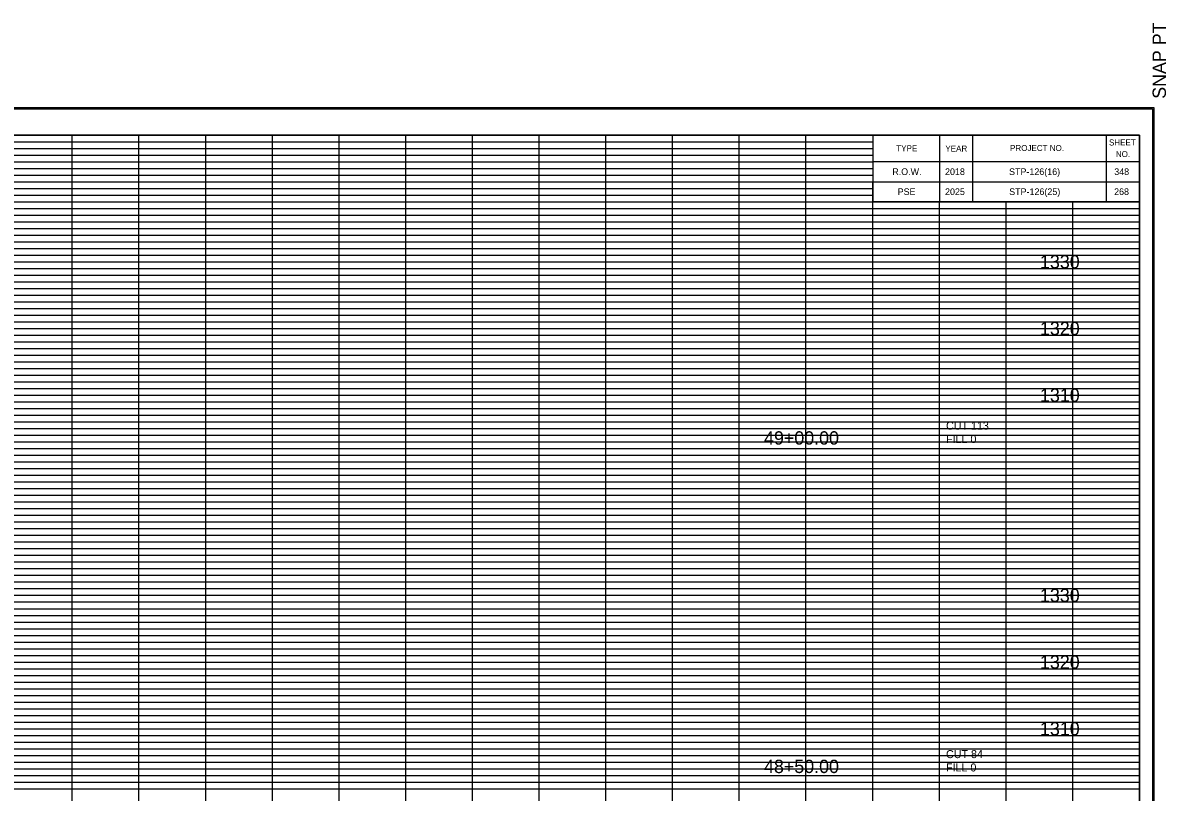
# Model space of a CAD drawing. Extents: x 980 to 1324, y 978 to 1767.
# Drawn here: x 1152.6 to 1324, y 1381.5 to 1496.8 of the extents above; entities that cross this region are included whole.
import ezdxf

# ---------------------------------------------------------------- set-up
doc = ezdxf.new("R2010")
doc.units = 0
for name, color, linetype in [('DESIGN - SCRATCH - User 1', 7, 'Continuous'), ('DESIGN - SHEET - Corner Text', 7, 'Continuous'), ('DESIGN - SHEET - Light Grid', 7, 'Continuous'), ('DESIGN - SHEET - Linework', 7, 'Continuous'), ('DESIGN - SHEET - Plot Shape', 7, 'Continuous'), ('DESIGN - TYPICAL - Text', 7, 'Continuous')]:
    doc.layers.add(name, color=color, linetype=linetype)

# ---------------------------------------------------------------- blocks, each defined once
blk = doc.blocks.new('XSTSHT')
at = {"layer": 'DESIGN - SCRATCH - User 1'}
for p, q in [((28.5, 20.45), (28.5, 20.45)), ((29.24, 20.45), (29.24, 20.45)), ((30.49, 20.45), (30.49, 20.45)), ((31.74, 20.45), (31.74, 20.45)), ((28.5, 20.15), (28.5, 20.15)), ((29.24, 20.15), (29.24, 20.15)), ((30.49, 20.15), (30.49, 20.15)), ((31.74, 20.15), (31.74, 20.15))]:
    blk.add_line(p, q, dxfattribs=at)
at = {"layer": 'DESIGN - SHEET - Light Grid'}
for p, q in [((8, 20.9), (16, 20.9)), ((8, 20.8), (16, 20.8)), ((16, 20.9), (24, 20.9)), ((16, 20.8), (24, 20.8)), ((24, 20.9), (28, 20.9)), ((24, 20.8), (28, 20.8)), ((8, 20.7), (16, 20.7)), ((8, 20.6), (16, 20.6)), ((16, 20.7), (24, 20.7)), ((16, 20.6), (24, 20.6)), ((24, 20.7), (28, 20.7)), ((24, 20.6), (28, 20.6)), ((8, 20.5), (16, 20.5)), ((8, 20.4), (16, 20.4)), ((16, 20.5), (24, 20.5)), ((16, 20.4), (24, 20.4)), ((24, 20.5), (28, 20.5)), ((24, 20.4), (28, 20.4)), ((8, 20.3), (16, 20.3)), ((16, 20.3), (24, 20.3)), ((24, 20.3), (28, 20.3)), ((8, 20.2), (16, 20.2)), ((8, 20.1), (16, 20.1)), ((16, 20.2), (24, 20.2)), ((16, 20.1), (24, 20.1)), ((24, 20.2), (28, 20.2)), ((24, 20.1), (28, 20.1)), ((8, 19.9), (16, 19.9)), ((16, 19.9), (24, 19.9)), ((24, 19.9), (32, 19.9)), ((8, 19.8), (16, 19.8)), ((16, 19.8), (24, 19.8)), ((24, 19.8), (32, 19.8)), ((8, 19.7), (16, 19.7)), ((8, 19.6), (16, 19.6)), ((16, 19.7), (24, 19.7)), ((16, 19.6), (24, 19.6)), ((24, 19.7), (32, 19.7)), ((24, 19.6), (32, 19.6)), ((8, 19.5), (16, 19.5)), ((8, 19.4), (16, 19.4)), ((16, 19.5), (24, 19.5)), ((16, 19.4), (24, 19.4)), ((24, 19.5), (32, 19.5)), ((24, 19.4), (32, 19.4)), ((8, 19.3), (16, 19.3)), ((8, 19.2), (16, 19.2)), ((16, 19.3), (24, 19.3)), ((16, 19.2), (24, 19.2)), ((24, 19.3), (32, 19.3)), ((24, 19.2), (32, 19.2)), ((8, 19.1), (16, 19.1)), ((16, 19.1), (24, 19.1)), ((24, 19.1), (32, 19.1)), ((8, 18.9), (16, 18.9)), ((16, 18.9), (24, 18.9)), ((24, 18.9), (32, 18.9)), ((8, 18.8), (16, 18.8)), ((8, 18.7), (16, 18.7)), ((16, 18.8), (24, 18.8)), ((16, 18.7), (24, 18.7)), ((24, 18.8), (32, 18.8)), ((24, 18.7), (32, 18.7)), ((8, 18.6), (16, 18.6)), ((16, 18.6), (24, 18.6)), ((24, 18.6), (32, 18.6)), ((8, 18.5), (16, 18.5)), ((8, 18.4), (16, 18.4)), ((16, 18.5), (24, 18.5)), ((16, 18.4), (24, 18.4)), ((24, 18.5), (32, 18.5)), ((24, 18.4), (32, 18.4)), ((8, 18.3), (16, 18.3)), ((8, 18.2), (16, 18.2)), ((16, 18.3), (24, 18.3)), ((16, 18.2), (24, 18.2)), ((24, 18.3), (32, 18.3)), ((24, 18.2), (32, 18.2)), ((8, 18.1), (16, 18.1)), ((16, 18.1), (24, 18.1)), ((24, 18.1), (32, 18.1)), ((8, 17.9), (16, 17.9)), ((16, 17.9), (24, 17.9)), ((24, 17.9), (32, 17.9)), ((8, 17.8), (16, 17.8)), ((8, 17.7), (16, 17.7)), ((16, 17.8), (24, 17.8)), ((16, 17.7), (24, 17.7)), ((24, 17.8), (32, 17.8)), ((24, 17.7), (32, 17.7)), ((8, 17.6), (16, 17.6)), ((8, 17.5), (16, 17.5)), ((16, 17.6), (24, 17.6)), ((16, 17.5), (24, 17.5)), ((24, 17.6), (32, 17.6)), ((24, 17.5), (32, 17.5)), ((8, 17.4), (16, 17.4)), ((16, 17.4), (24, 17.4)), ((24, 17.4), (32, 17.4)), ((8, 17.3), (16, 17.3)), ((8, 17.2), (16, 17.2)), ((16, 17.3), (24, 17.3)), ((16, 17.2), (24, 17.2)), ((24, 17.3), (32, 17.3)), ((24, 17.2), (32, 17.2)), ((8, 17.1), (16, 17.1)), ((16, 17.1), (24, 17.1)), ((24, 17.1), (32, 17.1)), ((8, 16.9), (16, 16.9)), ((8, 16.8), (16, 16.8)), ((16, 16.9), (24, 16.9)), ((16, 16.8), (24, 16.8)), ((24, 16.9), (32, 16.9)), ((24, 16.8), (32, 16.8)), ((8, 16.7), (16, 16.7)), ((16, 16.7), (24, 16.7)), ((24, 16.7), (32, 16.7)), ((8, 16.6), (16, 16.6)), ((8, 16.5), (16, 16.5)), ((16, 16.6), (24, 16.6)), ((16, 16.5), (24, 16.5)), ((24, 16.6), (32, 16.6)), ((24, 16.5), (32, 16.5)), ((8, 16.4), (16, 16.4)), ((8, 16.3), (16, 16.3)), ((16, 16.4), (24, 16.4)), ((16, 16.3), (24, 16.3)), ((24, 16.4), (32, 16.4)), ((24, 16.3), (32, 16.3)), ((8, 16.2), (16, 16.2)), ((16, 16.2), (24, 16.2)), ((24, 16.2), (32, 16.2)), ((8, 16.1), (16, 16.1)), ((16, 16.1), (24, 16.1)), ((24, 16.1), (32, 16.1)), ((8, 15.9), (16, 15.9)), ((8, 15.8), (16, 15.8)), ((16, 15.9), (24, 15.9)), ((16, 15.8), (24, 15.8)), ((24, 15.9), (32, 15.9)), ((24, 15.8), (32, 15.8)), ((8, 15.7), (16, 15.7)), ((8, 15.6), (16, 15.6)), ((16, 15.7), (24, 15.7)), ((16, 15.6), (24, 15.6)), ((24, 15.7), (32, 15.7)), ((24, 15.6), (32, 15.6)), ((8, 15.5), (16, 15.5)), ((16, 15.5), (24, 15.5)), ((24, 15.5), (32, 15.5)), ((8, 15.4), (16, 15.4)), ((8, 15.3), (16, 15.3)), ((16, 15.4), (24, 15.4)), ((16, 15.3), (24, 15.3)), ((24, 15.4), (32, 15.4)), ((24, 15.3), (32, 15.3)), ((8, 15.2), (16, 15.2)), ((8, 15.1), (16, 15.1)), ((16, 15.2), (24, 15.2)), ((16, 15.1), (24, 15.1)), ((24, 15.2), (32, 15.2)), ((24, 15.1), (32, 15.1)), ((8, 14.9), (16, 14.9)), ((8, 14.8), (16, 14.8)), ((16, 14.9), (24, 14.9)), ((16, 14.8), (24, 14.8)), ((24, 14.9), (32, 14.9)), ((24, 14.8), (32, 14.8)), ((8, 14.7), (16, 14.7)), ((8, 14.6), (16, 14.6)), ((16, 14.7), (24, 14.7)), ((16, 14.6), (24, 14.6)), ((24, 14.7), (32, 14.7)), ((24, 14.6), (32, 14.6)), ((8, 14.5), (16, 14.5)), ((8, 14.4), (16, 14.4)), ((16, 14.5), (24, 14.5)), ((16, 14.4), (24, 14.4)), ((24, 14.5), (32, 14.5)), ((24, 14.4), (32, 14.4)), ((8, 14.3), (16, 14.3)), ((16, 14.3), (24, 14.3)), ((24, 14.3), (32, 14.3)), ((8, 14.2), (16, 14.2)), ((8, 14.1), (16, 14.1)), ((16, 14.2), (24, 14.2)), ((16, 14.1), (24, 14.1)), ((24, 14.2), (32, 14.2)), ((24, 14.1), (32, 14.1)), ((8, 13.9), (16, 13.9)), ((16, 13.9), (24, 13.9)), ((24, 13.9), (32, 13.9)), ((8, 13.8), (16, 13.8)), ((16, 13.8), (24, 13.8)), ((24, 13.8), (32, 13.8)), ((8, 13.7), (16, 13.7)), ((8, 13.6), (16, 13.6)), ((16, 13.7), (24, 13.7)), ((16, 13.6), (24, 13.6)), ((24, 13.7), (32, 13.7)), ((24, 13.6), (32, 13.6)), ((8, 13.5), (16, 13.5)), ((8, 13.4), (16, 13.4)), ((16, 13.5), (24, 13.5)), ((16, 13.4), (24, 13.4)), ((24, 13.5), (32, 13.5)), ((24, 13.4), (32, 13.4)), ((8, 13.3), (16, 13.3)), ((8, 13.2), (16, 13.2)), ((16, 13.3), (24, 13.3)), ((16, 13.2), (24, 13.2)), ((24, 13.3), (32, 13.3)), ((24, 13.2), (32, 13.2)), ((8, 13.1), (16, 13.1)), ((16, 13.1), (24, 13.1)), ((24, 13.1), (32, 13.1)), ((8, 12.9), (16, 12.9)), ((16, 12.9), (24, 12.9)), ((24, 12.9), (32, 12.9)), ((8, 12.8), (16, 12.8)), ((8, 12.7), (16, 12.7)), ((16, 12.8), (24, 12.8)), ((16, 12.7), (24, 12.7)), ((24, 12.8), (32, 12.8)), ((24, 12.7), (32, 12.7)), ((8, 12.6), (16, 12.6)), ((16, 12.6), (24, 12.6)), ((24, 12.6), (32, 12.6)), ((8, 12.5), (16, 12.5)), ((8, 12.4), (16, 12.4)), ((16, 12.5), (24, 12.5)), ((16, 12.4), (24, 12.4)), ((24, 12.5), (32, 12.5)), ((24, 12.4), (32, 12.4)), ((8, 12.3), (16, 12.3)), ((8, 12.2), (16, 12.2)), ((16, 12.3), (24, 12.3)), ((16, 12.2), (24, 12.2)), ((24, 12.3), (32, 12.3)), ((24, 12.2), (32, 12.2)), ((8, 12.1), (16, 12.1)), ((16, 12.1), (24, 12.1)), ((24, 12.1), (32, 12.1)), ((8, 11.9), (16, 11.9)), ((16, 11.9), (24, 11.9)), ((24, 11.9), (32, 11.9)), ((8, 11.8), (16, 11.8)), ((8, 11.7), (16, 11.7)), ((16, 11.8), (24, 11.8)), ((16, 11.7), (24, 11.7)), ((24, 11.8), (32, 11.8)), ((24, 11.7), (32, 11.7)), ((8, 11.6), (16, 11.6)), ((8, 11.5), (16, 11.5)), ((16, 11.6), (24, 11.6)), ((16, 11.5), (24, 11.5)), ((24, 11.6), (32, 11.6)), ((24, 11.5), (32, 11.5)), ((8, 11.4), (16, 11.4)), ((16, 11.4), (24, 11.4)), ((24, 11.4), (32, 11.4)), ((8, 11.3), (16, 11.3)), ((8, 11.2), (16, 11.2)), ((16, 11.3), (24, 11.3)), ((16, 11.2), (24, 11.2)), ((24, 11.3), (32, 11.3)), ((24, 11.2), (32, 11.2))]:
    blk.add_line(p, q, dxfattribs=at)
at = {"layer": 'DESIGN - SHEET - Linework'}
for p, q in [((-1.823, 21.414), (32.217, 21.414)), ((32.217, 21.414), (32.217, -0.414)), ((16, 0), (16, 21)), ((17, 0), (17, 21)), ((18, 0), (18, 21)), ((19, 0), (19, 21)), ((20, 0), (20, 21)), ((21, 0), (21, 21)), ((22, 0), (22, 21)), ((23, 0), (23, 21)), ((24, 0), (24, 21)), ((25, 0), (25, 21)), ((26, 0), (26, 21)), ((27, 0), (27, 21)), ((0, 20), (28, 20)), ((28, 0), (28, 20)), ((29, 0), (29, 20)), ((30, 0), (30, 20)), ((31, 0), (31, 20)), ((0, 19), (32, 19)), ((0, 18), (32, 18)), ((0, 17), (32, 17)), ((0, 16), (32, 16)), ((0, 15), (32, 15)), ((0, 14), (32, 14)), ((0, 13), (32, 13)), ((0, 12), (32, 12))]:
    blk.add_line(p, q, dxfattribs=at)
for points in [[(0, 21), (0, 0), (32, 0), (32, 21), (0, 21)], [(28, 21), (28, 20), (32, 20), (32, 21), (31.5, 21), (31.5, 20), (29.5, 20), (29.5, 21), (29, 21), (29, 20), (32, 20), (28, 20), (28, 20.3), (32, 20.3), (32, 20.6), (28, 20.6)]]:
    blk.add_lwpolyline(points, dxfattribs=at)
at = {"layer": 'DESIGN - SHEET - Plot Shape'}
for points in [[(-1.803, 21.394), (32.197, 21.394), (32.197, -0.394), (-1.803, -0.394)], [(-0.85, 21), (32, 21), (32, -0.25), (-0.85, -0.25)]]:
    blk.add_lwpolyline(points, close=True, dxfattribs=at)
at = {"layer": 'DESIGN - SHEET - Corner Text'}
blk.add_text('  SNAP PT', height=0.2, rotation=90, dxfattribs=at).set_placement((32.397, 21.394))
for s, p in [('SHEET', (31.543, 20.843)), ('TYPE', (28.354, 20.756)), ('YEAR', (29.09, 20.752)), ('PROJECT NO.', (30.06, 20.76)), ('NO.', (31.646, 20.669))]:
    blk.add_text(s, height=0.09, dxfattribs=at).set_placement(p)

msp = doc.modelspace()

# ---------------------------------------------------------------- linework, layer by layer
at = {"layer": 'DESIGN - SHEET - Plot Shape'}
msp.add_lwpolyline([(991.5, 1267.5), (1320, 1267.5), (1320, 1480), (991.5, 1480)], close=True, dxfattribs=at)

# ---------------------------------------------------------------- block references
at = {"layer": 'DESIGN - SHEET - Plot Shape', "xscale": 10, "yscale": 10}
msp.add_blockref('XSTSHT', (1000, 1270), dxfattribs=at)

# ---------------------------------------------------------------- texts
at = {"layer": 'DESIGN - SHEET - Corner Text'}
for s, p in [('R.O.W.', (1282.94, 1474)), ('2018', (1290.85, 1474)), ('STP-126(16)', (1300.45, 1474)), ('348', (1316.22, 1474)), ('PSE', (1283.75, 1471)), ('2025', (1290.85, 1471)), ('STP-126(25)', (1300.47, 1471)), ('268', (1316.2, 1471))]:
    msp.add_text(s, height=1, dxfattribs=at).set_placement(p)
at = {"layer": 'DESIGN - TYPICAL - Text'}
for s, height, p in [('     1330     ', 2, (1301.37, 1460)), ('     1320     ', 2, (1301.37, 1450)), ('     1310     ', 2, (1301.37, 1440)), ('CUT 113', 1.2, (1291, 1435.83)), ('     49+00.00     ', 2, (1260, 1433.59)), ('FILL 0', 1.2, (1291, 1433.83)), ('     1330     ', 2, (1301.37, 1410)), ('     1320     ', 2, (1301.37, 1400)), ('     1310     ', 2, (1301.37, 1390)), ('CUT 84', 1.2, (1291, 1386.6)), ('     48+50.00     ', 2, (1260, 1384.36)), ('FILL 0', 1.2, (1291, 1384.6))]:
    msp.add_text(s, height=height, dxfattribs=at).set_placement(p)

doc.saveas('drawing.dxf')
